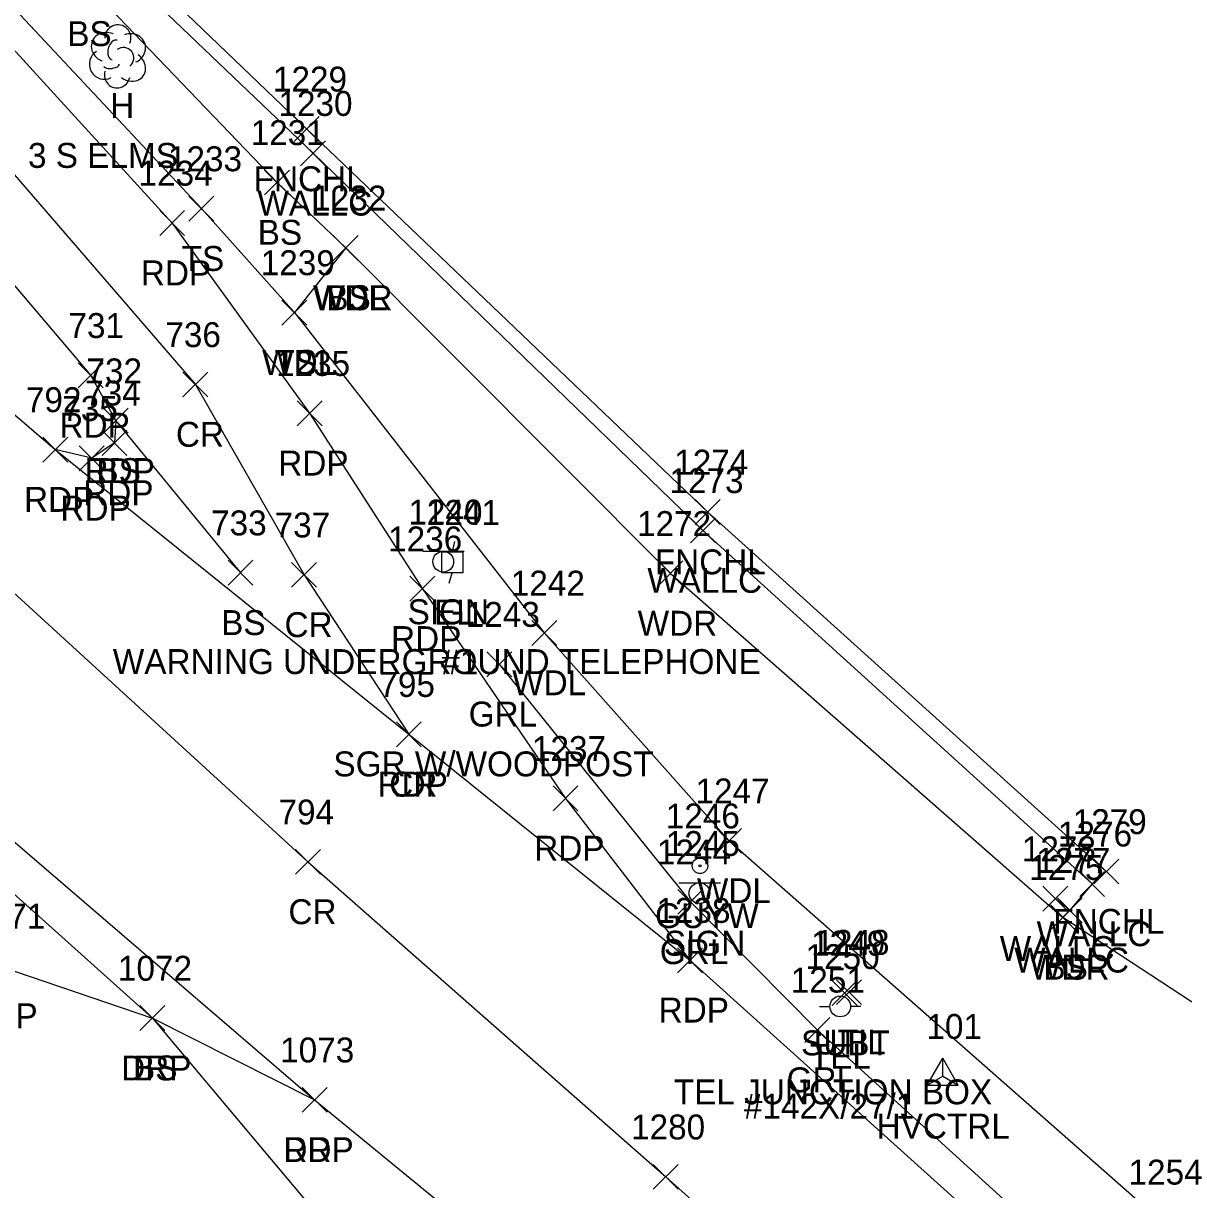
# Model space of a CAD drawing. Extents: x 1647133 to 1649138, y 411736 to 414924.
# Drawn here: x 1648842.3 to 1648935.4, y 411884.6 to 411978.2 of the extents above; entities that cross this region are included whole.
import ezdxf

# ---------------------------------------------------------------- set-up
doc = ezdxf.new("R2010")
doc.units = 0
for name, color, linetype in [('C_A', 7, 'Continuous'), ('C_I', 7, 'Continuous'), ('CPSM', 7, 'Continuous'), ('L_A', 7, 'Continuous'), ('L_C', 7, 'Continuous'), ('L_I', 7, 'Continuous'), ('L_TIC', 7, 'Continuous'), ('LAWA', 7, 'Continuous'), ('LELB', 7, 'Continuous'), ('LFNC', 7, 'Continuous'), ('LTD', 7, 'Continuous'), ('LW', 7, 'Continuous'), ('P_A', 7, 'Continuous'), ('P_I', 7, 'Continuous'), ('P_TIC', 7, 'Continuous'), ('PET', 7, 'Continuous'), ('PRC', 7, 'Continuous'), ('R_A', 7, 'Continuous'), ('R_C', 7, 'Continuous'), ('R_I', 7, 'Continuous'), ('R_TIC', 7, 'Continuous'), ('RDP', 7, 'Continuous'), ('RGR', 7, 'Continuous'), ('S_A', 7, 'Continuous'), ('S_C', 7, 'Continuous'), ('S_I', 7, 'Continuous'), ('SSGN', 7, 'Continuous'), ('U_A', 7, 'Continuous'), ('U_C', 7, 'Continuous'), ('U_I', 7, 'Continuous'), ('U_TIC', 7, 'Continuous'), ('UDEFAULT', 7, 'Continuous'), ('UEPT', 7, 'Continuous'), ('UP', 7, 'Continuous'), ('UPGW', 7, 'Continuous')]:
    doc.layers.add(name, color=color, linetype=linetype)

msp = doc.modelspace()

# ---------------------------------------------------------------- linework, layer by layer
at = {"layer": 'CPSM'}
for p, q in [((1648914.831, 411892.963), (1648916.081, 411895.128)), ((1648917.331, 411892.963), (1648916.081, 411895.128)), ((1648916.081, 411893.684), (1648916.081, 411895.128)), ((1648914.831, 411892.963), (1648916.081, 411893.684)), ((1648916.081, 411893.684), (1648916.081, 411893.684)), ((1648916.081, 411893.684), (1648917.331, 411892.963)), ((1648914.831, 411892.963), (1648917.331, 411892.963))]:
    msp.add_line(p, q, dxfattribs=at)
at = {"layer": 'L_TIC'}
for points in [[(1648864.02, 411968.719), (1648866.02, 411970.719)], [(1648866.02, 411968.719), (1648864.02, 411970.719)], [(1648864.538, 411966.762), (1648866.538, 411968.762)], [(1648866.538, 411966.762), (1648864.538, 411968.762)], [(1648861.655, 411964.419), (1648863.655, 411966.419)], [(1648863.655, 411964.419), (1648861.655, 411966.419)], [(1648855.58, 411962.322), (1648857.58, 411964.322)], [(1648857.58, 411962.322), (1648855.58, 411964.322)], [(1648867.166, 411959.17), (1648869.166, 411961.17)], [(1648869.166, 411959.17), (1648867.166, 411961.17)], [(1648867.166, 411959.17), (1648869.166, 411961.17)], [(1648869.166, 411959.17), (1648867.166, 411961.17)], [(1648867.166, 411959.17), (1648869.166, 411961.17)], [(1648869.166, 411959.17), (1648867.166, 411961.17)], [(1648863.038, 411953.98), (1648865.038, 411955.98)], [(1648865.038, 411953.98), (1648863.038, 411955.98)], [(1648863.038, 411953.98), (1648865.038, 411955.98)], [(1648865.038, 411953.98), (1648863.038, 411955.98)], [(1648848.709, 411945.294), (1648850.709, 411947.294)], [(1648850.709, 411945.294), (1648848.709, 411947.294)], [(1648896.223, 411937.969), (1648898.223, 411939.969)], [(1648898.223, 411937.969), (1648896.223, 411939.969)], [(1648895.838, 411936.49), (1648897.838, 411938.49)], [(1648897.838, 411936.49), (1648895.838, 411938.49)], [(1648858.718, 411933.096), (1648860.718, 411935.096)], [(1648860.718, 411933.096), (1648858.718, 411935.096)], [(1648893.234, 411933.043), (1648895.234, 411935.043)], [(1648895.234, 411933.043), (1648893.234, 411935.043)], [(1648883.104, 411928.267), (1648885.104, 411930.267)], [(1648885.104, 411928.267), (1648883.104, 411930.267)], [(1648897.933, 411911.583), (1648899.933, 411913.583)], [(1648899.933, 411911.583), (1648897.933, 411913.583)], [(1648928.213, 411909.119), (1648930.213, 411911.119)], [(1648930.213, 411909.119), (1648928.213, 411911.119)], [(1648927.08, 411908.127), (1648929.08, 411910.127)], [(1648929.08, 411908.127), (1648927.08, 411910.127)], [(1648924.128, 411906.94), (1648926.128, 411908.94)], [(1648926.128, 411906.94), (1648924.128, 411908.94)], [(1648925.287, 411906.011), (1648927.287, 411908.011)], [(1648927.287, 411906.011), (1648925.287, 411908.011)], [(1648924.726, 411905.442), (1648926.726, 411907.442)], [(1648926.726, 411905.442), (1648924.726, 411907.442)], [(1648924.726, 411905.442), (1648926.726, 411907.442)], [(1648926.726, 411905.442), (1648924.726, 411907.442)], [(1648851.646, 411897.353), (1648853.646, 411899.353)], [(1648853.646, 411897.353), (1648851.646, 411899.353)]]:
    msp.add_lwpolyline(points, dxfattribs=at)
at = {"layer": 'LAWA'}
for points in [[(1648868.166, 411960.17), (1648864.038, 411954.98), (1648884.104, 411929.267), (1648898.933, 411912.583), (1648933.692, 411881.993), (1648961.811, 411858.047), (1648999.602, 411820.727), (1649038.839, 411784.038)], [(1648868.166, 411960.17), (1648894.234, 411934.043), (1648925.726, 411906.442)]]:
    msp.add_lwpolyline(points, dxfattribs=at)
at = {"layer": 'LELB'}
for points in [[(1648820.342, 412002.003), (1648856.58, 411963.322), (1648864.038, 411954.98)], [(1648830.728, 411997.439), (1648847.368, 411981.365), (1648862.655, 411965.419), (1648868.166, 411960.17)], [(1648751.095, 411983.828), (1648760.092, 411978.22), (1648771.973, 411970.92), (1648795.546, 411950.439), (1648830.258, 411918.417), (1648852.646, 411898.353), (1648868.763, 411879.164), (1648878.386, 411860.923), (1648891.378, 411855.434), (1648912.798, 411838.201), (1648926.61, 411828.098), (1648926.491, 411825.939), (1648922.273, 411828.096)], [(1648849.709, 411946.294), (1648859.718, 411934.096)], [(1649052.269, 411798.129), (1649025.425, 411821.825), (1648997.34, 411845.482), (1648984.95, 411860.605), (1648974.496, 411869.317), (1648946.229, 411892.989), (1648925.726, 411906.442)]]:
    msp.add_lwpolyline(points, dxfattribs=at)
at = {"layer": 'LFNC'}
msp.add_lwpolyline([(1648849.624, 411984.488), (1648865.02, 411969.719), (1648897.223, 411938.969), (1648929.213, 411910.119)], dxfattribs=at)
at = {"layer": 'LTD'}
msp.add_line((1648849.822, 411975.592), (1648849.822, 411975.592), dxfattribs=at)
msp.add_line((1648849.822, 411975.592), (1648849.822, 411975.592), dxfattribs=at)
msp.add_arc((1648849.869, 411977.026), 1.047, 335.52715, 180.95627, dxfattribs=at)
for centre, major_axis, ratio, start_param, end_param in [((1648849.031, 411976.259), (1.21, -0.512), 0.895232, 1.570796, 4.712389), ((1648850.864, 411976.176), (-1.141, -0.483), 0.949671, 1.570796, 4.712389), ((1648849.614, 411976.05), (-0.208, -0.792), 0.645439, 3.141593, 6.283185), ((1648850.323, 411975.426), (-0.5, 0.667), 0.989748, 3.141593, 6.283185), ((1648848.739, 411974.884), (0.584, -1.042), 0.959034, 3.141593, 6.283185), ((1648850.823, 411974.759), (-1.09, 0.792), 0.841452, 1.570796, 4.712389), ((1648849.823, 411974.092), (0.265, 1.061), 0.942809, 1.570796, 4.712389), ((1648849.364, 411974.842), (-0.625, -0.083), 0.423636, 0, 3.141593)]:
    msp.add_ellipse(centre, major_axis=major_axis, ratio=ratio, start_param=start_param, end_param=end_param, dxfattribs=at)
at = {"layer": 'LW'}
msp.add_lwpolyline([(1648830.728, 411997.439), (1648820.132, 412007.636), (1648821.905, 412009.475), (1648849.198, 411983.406), (1648865.538, 411967.762), (1648896.838, 411937.49), (1648928.08, 411909.127), (1648926.287, 411907.011), (1648925.128, 411907.94)], dxfattribs=at)
at = {"layer": 'P_TIC'}
for points in [[(1648853.228, 411961.165), (1648855.228, 411963.165)], [(1648855.228, 411961.165), (1648853.228, 411963.165)], [(1648846.696, 411948.935), (1648848.696, 411950.935)], [(1648848.696, 411948.935), (1648846.696, 411950.935)], [(1648855.098, 411948.207), (1648857.098, 411950.207)], [(1648857.098, 411948.207), (1648855.098, 411950.207)], [(1648848.709, 411945.294), (1648850.709, 411947.294)], [(1648850.709, 411945.294), (1648848.709, 411947.294)], [(1648864.258, 411945.896), (1648866.258, 411947.896)], [(1648866.258, 411945.896), (1648864.258, 411947.896)], [(1648848.601, 411943.52), (1648850.601, 411945.52)], [(1648850.601, 411943.52), (1648848.601, 411945.52)], [(1648843.849, 411942.985), (1648845.849, 411944.985)], [(1648845.849, 411942.985), (1648843.849, 411944.985)], [(1648843.849, 411942.985), (1648845.849, 411944.985)], [(1648845.849, 411942.985), (1648843.849, 411944.985)], [(1648846.769, 411942.282), (1648848.769, 411944.282)], [(1648848.769, 411942.282), (1648846.769, 411944.282)], [(1648863.815, 411932.931), (1648865.815, 411934.931)], [(1648865.815, 411932.931), (1648863.815, 411934.931)], [(1648873.312, 411931.811), (1648875.312, 411933.811)], [(1648875.312, 411931.811), (1648873.312, 411933.811)], [(1648872.225, 411920.132), (1648874.225, 411922.132)], [(1648874.225, 411920.132), (1648872.225, 411922.132)], [(1648872.225, 411920.132), (1648874.225, 411922.132)], [(1648874.225, 411920.132), (1648872.225, 411922.132)], [(1648884.803, 411914.985), (1648886.803, 411916.985)], [(1648886.803, 411914.985), (1648884.803, 411916.985)], [(1648864.129, 411909.894), (1648866.129, 411911.894)], [(1648866.129, 411909.894), (1648864.129, 411911.894)], [(1648894.792, 411901.999), (1648896.792, 411903.999)], [(1648896.792, 411901.999), (1648894.792, 411903.999)], [(1648894.792, 411901.999), (1648896.792, 411903.999)], [(1648896.792, 411901.999), (1648894.792, 411903.999)], [(1648864.668, 411890.795), (1648866.668, 411892.795)], [(1648866.668, 411890.795), (1648864.668, 411892.795)], [(1648892.845, 411884.618), (1648894.845, 411886.618)], [(1648894.845, 411884.618), (1648892.845, 411886.618)]]:
    msp.add_lwpolyline(points, dxfattribs=at)
at = {"layer": 'PET'}
for points in [[(1648818.001, 412063.558), (1648810.494, 412053.715), (1648791.901, 412040.154), (1648791.666, 412033.115), (1648794.121, 412026.773), (1648798.944, 412021.85), (1648819.062, 412000.668), (1648854.228, 411962.165), (1648865.258, 411946.896), (1648874.312, 411932.811), (1648885.803, 411915.985), (1648895.792, 411902.999)], [(1648755.318, 411988.116), (1648772.85, 411971.957), (1648796.64, 411951.338), (1648831.689, 411920.965), (1648865.668, 411891.795), (1648882.412, 411878.076), (1648919.238, 411845.27), (1648942.739, 411824.946), (1648978.242, 411792.709), (1649017.207, 411756.44)], [(1648794.521, 411987.621), (1648826.406, 411959.789), (1648844.849, 411943.985), (1648873.225, 411921.132), (1648895.792, 411902.999), (1648925.88, 411875.913), (1648954.391, 411850.184), (1648992.641, 411815.073), (1649033.549, 411777.708)], [(1648835.917, 411963.758), (1648847.696, 411949.935), (1648849.709, 411946.294), (1648849.601, 411944.52), (1648847.769, 411943.282), (1648844.849, 411943.985)]]:
    msp.add_lwpolyline(points, dxfattribs=at)
at = {"layer": 'PRC'}
for points in [[(1648523.855, 412428.164), (1648541.762, 412388.819), (1648560.786, 412347.218), (1648578.952, 412307.656), (1648596.522, 412268.849), (1648615.514, 412228.06), (1648629.383, 412198.525), (1648645.407, 412164.541), (1648659.578, 412134.14), (1648672.041, 412110.748), (1648683.898, 412091.11), (1648700.383, 412068.335), (1648715.839, 412049.98), (1648739.601, 412024.905), (1648761.868, 412004.355), (1648787.636, 411981.064), (1648820.993, 411950.624), (1648837.381, 411936.249), (1648865.129, 411910.894), (1648893.845, 411885.618), (1648930.35, 411852.903), (1648951.421, 411834.103), (1648988.1, 411800.425), (1649025.041, 411766.663)], [(1648664.816, 412155.812), (1648676.979, 412144.697), (1648692.804, 412127.015), (1648705.779, 412111.7), (1648725.575, 412089.279), (1648736.199, 412077.337), (1648750.767, 412061.914), (1648770.244, 412040.325), (1648787.372, 412023.03), (1648802.926, 412006.988), (1648820.913, 411988.588), (1648839.835, 411968.01), (1648856.098, 411949.207), (1648864.815, 411933.931), (1648873.225, 411921.132)]]:
    msp.add_lwpolyline(points, dxfattribs=at)
at = {"layer": 'R_TIC'}
for points in [[(1648879.489, 411925.756), (1648881.489, 411927.756)], [(1648881.489, 411925.756), (1648879.489, 411927.756)], [(1648894.83, 411906.685), (1648896.83, 411908.685)], [(1648896.83, 411906.685), (1648894.83, 411908.685)], [(1648851.646, 411897.353), (1648853.646, 411899.353)], [(1648853.646, 411897.353), (1648851.646, 411899.353)], [(1648905.011, 411896.402), (1648907.011, 411898.402)], [(1648907.011, 411896.402), (1648905.011, 411898.402)], [(1648864.668, 411890.795), (1648866.668, 411892.795)], [(1648866.668, 411890.795), (1648864.668, 411892.795)]]:
    msp.add_lwpolyline(points, dxfattribs=at)
at = {"layer": 'RDP'}
msp.add_lwpolyline([(1648829.772, 411917.188), (1648825.509, 411913.413), (1648840.301, 411902.539), (1648852.646, 411898.353), (1648865.668, 411891.795)], dxfattribs=at)
at = {"layer": 'RGR'}
msp.add_lwpolyline([(1648880.489, 411926.756), (1648895.83, 411907.685), (1648906.011, 411897.402), (1648927.465, 411877.904), (1648955.921, 411852.749), (1648995.156, 411817.246), (1649035.903, 411780.089)], dxfattribs=at)
at = {"layer": 'SSGN'}
for p, q in [((1648874.344, 411935.821), (1648877.677, 411935.821)), ((1648875.99, 411934.987), (1648875.99, 411934.987)), ((1648894.913, 411909.216), (1648898.246, 411909.216)), ((1648896.56, 411908.383), (1648896.56, 411908.383))]:
    msp.add_line(p, q, dxfattribs=at)
for centre in [(1648875.99, 411934.987), (1648896.56, 411908.383)]:
    msp.add_circle(centre, 0.833, dxfattribs=at)
at = {"layer": 'U_TIC'}
for points in [[(1648907.217, 411899.365), (1648909.217, 411901.365)], [(1648909.217, 411899.365), (1648907.217, 411901.365)]]:
    msp.add_lwpolyline(points, dxfattribs=at)
at = {"layer": 'UDEFAULT'}
for points in [[(1648907.558, 411899.434), (1648909.558, 411901.434)], [(1648909.558, 411899.434), (1648907.558, 411901.434)]]:
    msp.add_lwpolyline(points, dxfattribs=at)
at = {"layer": 'UEPT'}
for p, q in [((1648876.885, 411936.604), (1648876.719, 411935.771)), ((1648875.885, 411934.104), (1648875.885, 411935.771)), ((1648875.885, 411935.771), (1648877.552, 411935.771)), ((1648876.719, 411934.938), (1648876.719, 411934.938)), ((1648877.552, 411935.771), (1648877.552, 411934.104)), ((1648877.552, 411934.104), (1648875.885, 411934.104)), ((1648876.469, 411933.271), (1648876.719, 411934.104))]:
    msp.add_line(p, q, dxfattribs=at)
at = {"layer": 'UP'}
for p, q in [((1648906.198, 411899.281), (1648907.024, 411899.281)), ((1648907.857, 411899.287), (1648907.857, 411899.287)), ((1648909.524, 411899.287), (1648908.69, 411899.287)), ((1648908.69, 411899.287), (1648908.69, 411899.287)), ((1648909.524, 411899.287), (1648909.524, 411899.287))]:
    msp.add_line(p, q, dxfattribs=at)
msp.add_circle((1648907.857, 411899.287), 0.833, dxfattribs=at)
at = {"layer": 'UPGW'}
for radius in [0.625, 0.0833]:
    msp.add_circle((1648896.6, 411910.577), radius, dxfattribs=at)

# ---------------------------------------------------------------- texts
at = {"layer": 'C_A'}
msp.add_text('HVCTRL', height=2, dxfattribs=at).set_placement((1648910.774, 411888.684))
at = {"layer": 'C_I'}
msp.add_text('101', height=2, dxfattribs=at).set_placement((1648914.774, 411896.684))
at = {"layer": 'L_A'}
for s, p in [('BS', (1648845.809, 411976.365)), ('H', (1648849.256, 411970.592)), ('FNCHL', (1648860.768, 411964.719)), ('WALLC', (1648861.074, 411962.762)), ('BS', (1648861.096, 411960.419)), ('TS', (1648854.99, 411958.322)), ('WDR', (1648865.528, 411955.17)), ('WDL', (1648865.583, 411955.17)), ('BS', (1648866.607, 411955.17)), ('WDL', (1648861.455, 411949.98)), ('TS', (1648862.447, 411949.98)), ('BS', (1648848.15, 411941.294)), ('FNCHL', (1648892.971, 411933.969)), ('WALLC', (1648892.373, 411932.49)), ('BS', (1648858.159, 411929.096)), ('WDR', (1648891.596, 411929.043)), ('WDL', (1648881.521, 411924.267)), ('WDL', (1648896.35, 411907.583)), ('FNCHL', (1648924.961, 411905.119)), ('WALLC', (1648923.616, 411904.127)), ('WALLC', (1648920.663, 411902.94)), ('WALLC', (1648921.822, 411902.011)), ('WDR', (1648923.089, 411901.442)), ('BS', (1648924.167, 411901.442)), ('BS', (1648851.087, 411893.353))]:
    msp.add_text(s, height=2, dxfattribs=at).set_placement(p)
at = {"layer": 'L_C'}
msp.add_text('3 S ELMS', height=2, dxfattribs=at).set_placement((1648842.657, 411966.592))
at = {"layer": 'L_I'}
for s, p in [('1229', (1648862.319, 411972.719)), ('1230', (1648862.759, 411970.762)), ('1231', (1648860.529, 411968.419)), ('1233', (1648853.888, 411966.322)), ('1232', (1648865.473, 411963.17)), ('1232', (1648865.473, 411963.17)), ('1232', (1648865.473, 411963.17)), ('1239', (1648861.337, 411957.98)), ('1239', (1648861.337, 411957.98)), ('732', (1648847.347, 411949.294)), ('1274', (1648894.53, 411941.969)), ('1273', (1648894.145, 411940.49)), ('733', (1648857.356, 411937.096)), ('1272', (1648891.541, 411937.043)), ('1242', (1648881.411, 411932.267)), ('1247', (1648896.24, 411915.583)), ('1279', (1648926.512, 411913.119)), ('1276', (1648925.332, 411912.127)), ('1278', (1648922.435, 411910.94)), ('1275', (1648923.033, 411909.442)), ('1275', (1648923.033, 411909.442)), ('1277', (1648923.594, 411910.011)), ('1072', (1648849.875, 411901.353)), ('1254', (1648930.999, 411884.993))]:
    msp.add_text(s, height=2, dxfattribs=at).set_placement(p)
at = {"layer": 'P_A'}
for s, p in [('RDP', (1648851.716, 411957.165)), ('RDP', (1648845.184, 411944.935)), ('CR', (1648854.532, 411944.207)), ('RDP', (1648847.197, 411941.294)), ('RDP', (1648862.746, 411941.896)), ('RDP', (1648847.089, 411939.52)), ('RDP', (1648842.338, 411938.985)), ('RDP', (1648842.338, 411938.985)), ('RDP', (1648845.257, 411938.282)), ('CR', (1648863.248, 411928.931)), ('RDP', (1648871.8, 411927.811)), ('RDP', (1648870.713, 411916.132)), ('CR', (1648871.658, 411916.132)), ('RDP', (1648883.291, 411910.985)), ('CR', (1648863.563, 411905.894)), ('RDP', (1648893.28, 411897.999)), ('RDP', (1648893.28, 411897.999)), ('RDP', (1648863.156, 411886.795))]:
    msp.add_text(s, height=2, dxfattribs=at).set_placement(p)
at = {"layer": 'P_I'}
for s, p in [('1234', (1648851.535, 411965.165)), ('731', (1648845.901, 411952.935)), ('736', (1648853.681, 411952.207)), ('1235', (1648862.565, 411949.896)), ('732', (1648847.347, 411949.294)), ('792', (1648842.487, 411946.985)), ('792', (1648842.487, 411946.985)), ('734', (1648847.239, 411947.52)), ('735', (1648845.407, 411946.282)), ('737', (1648862.453, 411936.931)), ('1236', (1648871.564, 411935.811)), ('795', (1648870.863, 411924.132)), ('795', (1648870.863, 411924.132)), ('1237', (1648883.11, 411918.985)), ('794', (1648862.767, 411913.894)), ('1238', (1648893.099, 411905.999)), ('1238', (1648893.099, 411905.999)), ('1073', (1648862.897, 411894.795)), ('1280', (1648891.065, 411888.618))]:
    msp.add_text(s, height=2, dxfattribs=at).set_placement(p)
at = {"layer": 'R_A'}
for s, p in [('GRL', (1648878.032, 411921.756)), ('GRL', (1648893.373, 411902.685)), ('DRP', (1648837.789, 411897.539)), ('DRP', (1648850.134, 411893.353)), ('GRL', (1648903.554, 411892.402)), ('DRP', (1648863.156, 411886.795))]:
    msp.add_text(s, height=2, dxfattribs=at).set_placement(p)
at = {"layer": 'R_C'}
msp.add_text('SGR W/WOODPOST', height=2, dxfattribs=at).set_placement((1648867.174, 411917.756))
at = {"layer": 'R_I'}
for s, p in [('1243', (1648877.796, 411929.756)), ('1244', (1648893.137, 411910.685)), ('1071', (1648838.096, 411905.539)), ('1072', (1648849.875, 411901.353)), ('1251', (1648903.885, 411900.402)), ('1073', (1648862.897, 411894.795))]:
    msp.add_text(s, height=2, dxfattribs=at).set_placement(p)
at = {"layer": 'S_A'}
for p in [(1648873.128, 411929.967), (1648893.698, 411903.363)]:
    msp.add_text('SIGN', height=2, dxfattribs=at).set_placement(p)
at = {"layer": 'S_C'}
msp.add_text('WARNING UNDERGROUND TELEPHONE', height=2, dxfattribs=at).set_placement((1648849.467, 411925.967))
at = {"layer": 'S_I'}
for s, p in [('1240', (1648873.191, 411937.967)), ('1245', (1648893.847, 411911.363))]:
    msp.add_text(s, height=2, dxfattribs=at).set_placement(p)
at = {"layer": 'U_A'}
for s, p in [('EL', (1648875.254, 411929.938)), ('GUYW', (1648892.994, 411905.577)), ('UTIL', (1648905.723, 411895.434)), ('SUBT', (1648904.713, 411895.365)), ('TEL', (1648905.416, 411894.287))]:
    msp.add_text(s, height=2, dxfattribs=at).set_placement(p)
at = {"layer": 'U_C'}
for s, p in [('#1', (1648875.821, 411925.938)), ('TEL JUNCTION BOX', (1648894.495, 411891.434)), ('#142X/27/1', (1648900.125, 411890.287))]:
    msp.add_text(s, height=2, dxfattribs=at).set_placement(p)
at = {"layer": 'U_I'}
for s, p in [('1241', (1648874.593, 411937.938)), ('1246', (1648893.852, 411913.577)), ('1249', (1648905.516, 411903.365)), ('1248', (1648905.865, 411903.434)), ('1250', (1648905.077, 411902.287))]:
    msp.add_text(s, height=2, dxfattribs=at).set_placement(p)

doc.saveas('drawing.dxf')
